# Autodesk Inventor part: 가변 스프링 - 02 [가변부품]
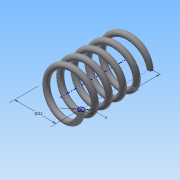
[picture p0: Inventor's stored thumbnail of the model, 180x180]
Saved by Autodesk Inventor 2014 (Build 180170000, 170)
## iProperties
Created: 2015-09
Part Number: 가변 스프링 - 02 [가변부품]
Material: 강철, 탄소
Document SubType Name: Modeling
Designer: study
Density: 1 g/cm^3
Appearance: 반연마
Author: study
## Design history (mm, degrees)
sketch "스케치1"
  geometry: L1 (0, 0)-(11, 0); L2 (11, 0)-(11, 36.561); L3 (11, 36.561)-(0, 36.561); L4 (0, 36.561)-(0, 0); C1 r 1.5 at (11, 0)
  constraints: 8 end point, 2 parallel, 1 centre point, 1 coincident, 1 horizontal, 1 perpendicular
  dimensions: "d0" = 22 diameter of L2 L4; "d1" = 36.5612 distance between parallel lines of L3 L1 (derived); "d2" = 3 diameter of C1
feature "코일1" sketch "스케치1" pitch "d3" = 10; turns "d5" = 5; dims "d4" = 36.5612 (= d1), "d6" = 0, angle "d7" = 90 deg, angle "d8" = 90 deg, "d9" = 0, "d10" = 0
node "작업 평면1"
sketch "스케치2"
  geometry: L1 (-12.5, 0)-(-9.5, 0) reference; L2 (-12.5, 0)-(-9.5, 0) reference; 1 further point
  constraints: 2 horizontal alignment
extrude "돌출1" cut sketch "스케치2" stored distance "d12" = 10; taper "d13" = 0 deg
node "작업 평면2"
sketch "스케치3"
  geometry: L1 (-9.5, 0)-(-12.5, 0) reference; 1 further point
  constraints: 1 horizontal alignment
extrude "돌출2" cut sketch "스케치3" stored distance "d15" = 10; taper "d16" = 0 deg
node "솔리드1"
node "절단 모서리 투영1"
node "절단 모서리 투영2"
node "절단 모서리 투영3"
other parameters: "d11" = 0, "d14" = 36.5612 (= d1)
